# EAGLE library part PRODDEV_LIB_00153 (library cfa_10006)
ICL7660CSA, IC VOLT CONV CMOS SW-CAP 8-SOIC
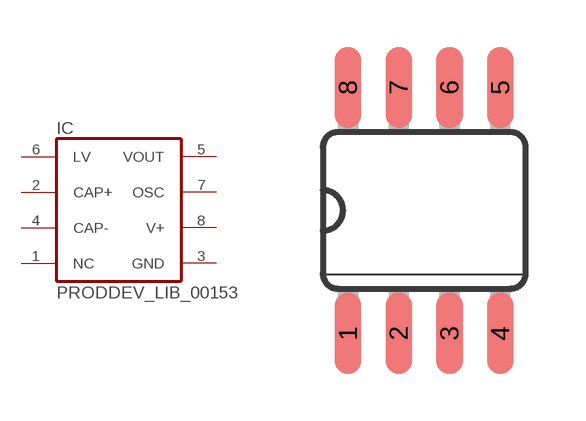
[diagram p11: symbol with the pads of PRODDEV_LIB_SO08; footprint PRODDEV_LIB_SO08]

Designator prefix IC

## PRODDEV_LIB_00153  [PRODDEV_LIB_SO08]
1  NC  nc
2  CAP+  pas
3  GND  pwr
4  CAP-  pas
5  VOUT  out
6  LV  pas
7  OSC  out
8  V+  pwr

## Footprint PRODDEV_LIB_SO08 (pad centres in mm)
Small Outline Package
smd 0.66 x 2.032: 1 -1.905,-3.073; 2 -0.635,-3.073; 3 0.635,-3.073; 4 1.905,-3.073; 5 1.905,3.073; 6 0.635,3.073; 7 -0.635,3.073; 8 -1.905,3.073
